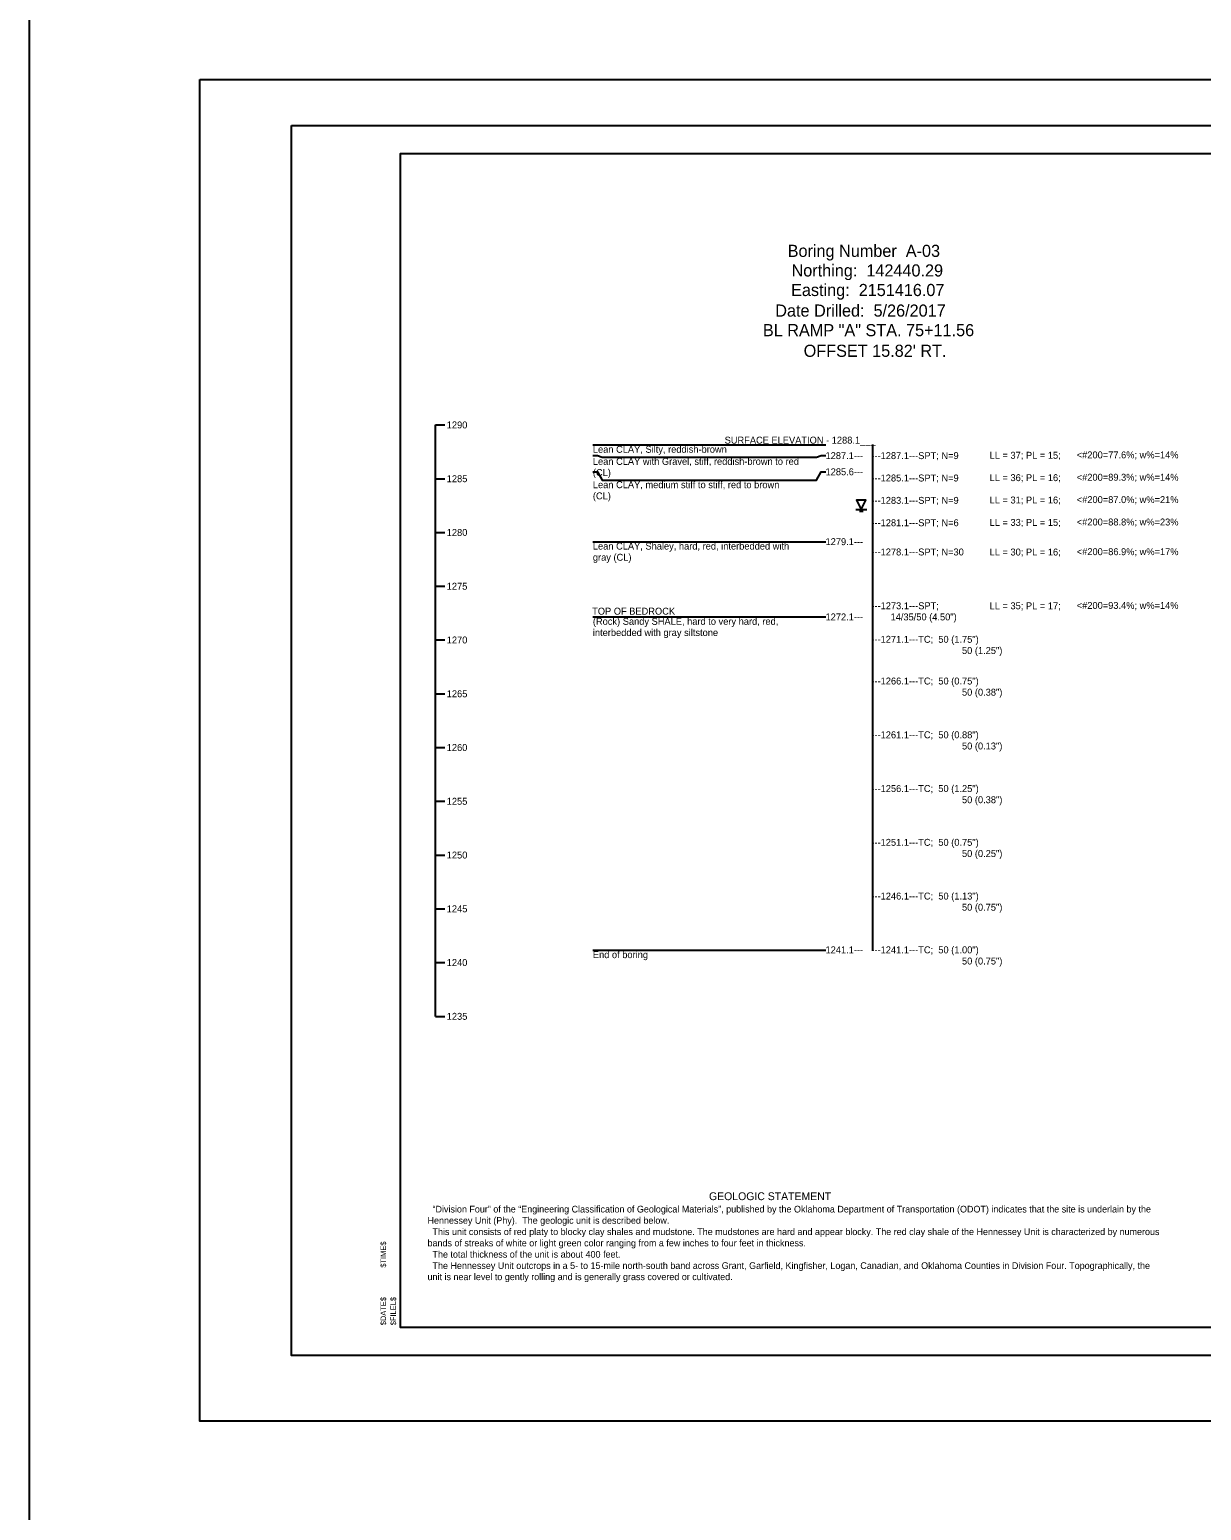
# Model space of a CAD drawing. Extents: x 2150161.5 to 2150203.1, y 143779.5 to 143868.5.
# Drawn here: x 2150161.53 to 2150182.49, y 143808.09 to 143834.58 of the extents above; entities that cross this region are included whole.
import ezdxf

# ---------------------------------------------------------------- set-up
doc = ezdxf.new("R2010")
doc.units = 0
for name, color, linetype in [('Default', 7, 'Continuous'), ('S', 7, 'Continuous'), ('SHT_Plot_Shape_Full', 7, 'Continuous'), ('SHT_Plot_Shape_Half', 7, 'Continuous'), ('SHT_Plot_Stamp', 7, 'Continuous'), ('SHT_Sheet_Border', 7, 'Continuous'), ('Text', 7, 'Continuous')]:
    doc.layers.add(name, color=color, linetype=linetype)

# ---------------------------------------------------------------- blocks, each defined once
blk = doc.blocks.new('Stamp_Plot_Stamp')
at = {"layer": 'SHT_Plot_Stamp'}
for s, p in [('$TIME$', (1.695, 1.572)), ('$DATE$', (1.695, 0.542)), ('$FILEL$', (1.873, 0.542))]:
    blk.add_text(s, height=0.1, rotation=90, dxfattribs=at).set_placement(p)
blk = doc.blocks.new('DGRFC_WTLEV1')
at = {"layer": 'Default'}
for points in [[(-0.0127, 0), (0.0127, 0)], [(0, 0), (0.0106, 0.0212), (-0.0106, 0.0212), (0, 0)], [(-0.0042, -0.0042), (0.0042, -0.0042)]]:
    blk.add_lwpolyline(points, dxfattribs=at)

msp = doc.modelspace()

# ---------------------------------------------------------------- linework, layer by layer
at = {"layer": 'Default'}
msp.add_line((2150168.788, 143816.93), (2150168.788, 143827.507), dxfattribs=at)
for points in [[(2150168.788, 143827.507), (2150168.955, 143827.507)], [(2150171.606, 143827.15), (2150175.773, 143827.15)], [(2150176.606, 143827.16), (2150176.606, 143818.111)], [(2150171.606, 143826.958), (2150171.69, 143826.958), (2150171.773, 143826.933), (2150175.606, 143826.933), (2150175.69, 143826.958), (2150175.773, 143826.958)], [(2150168.788, 143826.545), (2150168.955, 143826.545)], [(2150171.606, 143826.669), (2150171.69, 143826.669), (2150171.773, 143826.517), (2150175.606, 143826.517), (2150175.69, 143826.669), (2150175.773, 143826.669)], [(2150176.606, 143826.708), (2150176.606, 143819.202)], [(2150168.788, 143825.584), (2150168.955, 143825.584)], [(2150171.606, 143825.419), (2150175.773, 143825.419)], [(2150168.788, 143824.622), (2150168.955, 143824.622)], [(2150171.606, 143824.073), (2150175.773, 143824.073)], [(2150168.788, 143823.661), (2150168.955, 143823.661)], [(2150168.788, 143822.699), (2150168.955, 143822.699)], [(2150168.788, 143821.738), (2150168.955, 143821.738)], [(2150168.788, 143820.776), (2150168.955, 143820.776)], [(2150168.788, 143819.815), (2150168.955, 143819.815)], [(2150168.788, 143818.853), (2150168.955, 143818.853)], [(2150168.788, 143818.853), (2150168.955, 143818.853)], [(2150171.606, 143818.111), (2150175.773, 143818.111)], [(2150168.788, 143817.892), (2150168.955, 143817.892)], [(2150168.788, 143817.892), (2150168.955, 143817.892)], [(2150168.788, 143816.93), (2150168.955, 143816.93)], [(2150168.788, 143816.93), (2150168.955, 143816.93)], [(2150168.788, 143816.93), (2150168.955, 143816.93)]]:
    msp.add_lwpolyline(points, dxfattribs=at)
at = {"layer": 'S'}
msp.add_lwpolyline([(2150161.53, 143868.477), (2150203.071, 143868.477), (2150203.071, 143779.536), (2150161.53, 143779.536)], close=True, dxfattribs=at)
at = {"layer": 'SHT_Plot_Shape_Full'}
msp.add_lwpolyline([(2150164.575, 143833.688), (2150200.575, 143833.688), (2150200.575, 143809.688), (2150164.575, 143809.688)], close=True, dxfattribs=at)
at = {"layer": 'SHT_Plot_Shape_Half'}
msp.add_lwpolyline([(2150166.212, 143832.863), (2150200.212, 143832.863), (2150200.212, 143810.863), (2150166.212, 143810.863)], close=True, dxfattribs=at)
at = {"layer": 'SHT_Sheet_Border'}
msp.add_lwpolyline([(2150199.662, 143811.363), (2150168.162, 143811.363), (2150168.162, 143832.363), (2150199.662, 143832.363)], close=True, dxfattribs=at)

# ---------------------------------------------------------------- block references
at = {"layer": 'Default', "xscale": 7.873999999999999, "yscale": 7.873999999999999}
msp.add_blockref('DGRFC_WTLEV1', (2150176.408, 143825.996), dxfattribs=at)
at = {"layer": 'SHT_Plot_Stamp'}
msp.add_blockref('Stamp_Plot_Stamp', (2150166.212, 143810.863), dxfattribs=at)

# ---------------------------------------------------------------- texts
at = {"layer": 'Default'}
for s, height, p in [('Boring Number  A-03', 0.217, (2150175.091, 143830.512)), ('Northing:  142440.29', 0.217, (2150175.16, 143830.162)), ('Easting:  2151416.07', 0.217, (2150175.152, 143829.812)), ('Date Drilled:  5/26/2017', 0.217, (2150174.869, 143829.444)), ('BL RAMP "A" STA. 75+11.56', 0.217, (2150174.648, 143829.094)), ("OFFSET 15.82' RT.", 0.217, (2150175.377, 143828.725)), ('1290', 0.124, (2150168.992, 143827.445)), ('Lean CLAY, Silty, reddish-brown', 0.124, (2150171.606, 143827.009)), ('SURFACE ELEVATION - 1288.1___', 0.124, (2150173.963, 143827.173)), ('Lean CLAY with Gravel, stiff, reddish-brown to red', 0.124, (2150171.606, 143826.793)), ('1287.1---', 0.124, (2150175.768, 143826.896)), ('---1287.1---SPT; N=9', 0.124, (2150176.588, 143826.896)), ('LL = 37; PL = 15;', 0.124, (2150178.703, 143826.902)), ('<#200=77.6%; w%=14%', 0.124, (2150180.262, 143826.909)), ('1285', 0.124, (2150168.992, 143826.483)), ('(CL)', 0.124, (2150171.606, 143826.593)), ('1285.6---', 0.124, (2150175.768, 143826.607)), ('---1285.1---SPT; N=9', 0.124, (2150176.588, 143826.496)), ('LL = 36; PL = 16;', 0.124, (2150178.703, 143826.502)), ('<#200=89.3%; w%=14%', 0.124, (2150180.262, 143826.509)), ('(CL)', 0.124, (2150171.606, 143826.176)), ('Lean CLAY, medium stiff to stiff, red to brown', 0.124, (2150171.606, 143826.376)), ('---1283.1---SPT; N=9', 0.124, (2150176.588, 143826.096)), ('LL = 31; PL = 16;', 0.124, (2150178.703, 143826.102)), ('<#200=87.0%; w%=21%', 0.124, (2150180.262, 143826.109)), ('---1281.1---SPT; N=6', 0.124, (2150176.588, 143825.696)), ('LL = 33; PL = 15;', 0.124, (2150178.703, 143825.702)), ('<#200=88.8%; w%=23%', 0.124, (2150180.262, 143825.709)), ('1280', 0.124, (2150168.992, 143825.522)), ('1279.1---', 0.124, (2150175.768, 143825.357)), ('gray (CL)', 0.124, (2150171.606, 143825.078)), ('Lean CLAY, Shaley, hard, red, interbedded with', 0.124, (2150171.606, 143825.278)), ('---1278.1---SPT; N=30', 0.124, (2150176.588, 143825.173)), ('LL = 30; PL = 16;', 0.124, (2150178.703, 143825.172)), ('<#200=86.9%; w%=17%', 0.124, (2150180.262, 143825.178)), ('1275', 0.124, (2150168.992, 143824.56)), ('TOP OF BEDROCK', 0.124, (2150171.593, 143824.114)), ('1272.1---', 0.124, (2150175.768, 143824.011)), ('---1273.1---SPT;', 0.124, (2150176.588, 143824.211)), ('14/35/50 (4.50")', 0.124, (2150176.931, 143824.011)), ('LL = 35; PL = 17;', 0.124, (2150178.703, 143824.21)), ('<#200=93.4%; w%=14%', 0.124, (2150180.262, 143824.217)), ('(Rock) Sandy SHALE, hard to very hard, red,', 0.124, (2150171.606, 143823.932)), ('interbedded with gray siltstone', 0.124, (2150171.606, 143823.732)), ('1270', 0.124, (2150168.992, 143823.599)), ('---1271.1---TC;  50 (1.75")', 0.124, (2150176.588, 143823.611)), ('50 (1.25")', 0.124, (2150178.209, 143823.411)), ('---1266.1---TC;  50 (0.75")', 0.124, (2150176.588, 143822.865)), ('1265', 0.124, (2150168.992, 143822.637)), ('50 (0.38")', 0.124, (2150178.209, 143822.665)), ('---1261.1---TC;  50 (0.88")', 0.124, (2150176.588, 143821.903)), ('1260', 0.124, (2150168.992, 143821.676)), ('50 (0.13")', 0.124, (2150178.209, 143821.703)), ('---1256.1---TC;  50 (1.25")', 0.124, (2150176.588, 143820.942)), ('1255', 0.124, (2150168.992, 143820.714)), ('50 (0.38")', 0.124, (2150178.209, 143820.742)), ('---1251.1---TC;  50 (0.75")', 0.124, (2150176.588, 143819.98)), ('50 (0.25")', 0.124, (2150178.209, 143819.78)), ('1250', 0.124, (2150168.992, 143819.753)), ('---1246.1---TC;  50 (1.13")', 0.124, (2150176.588, 143819.019)), ('1245', 0.124, (2150168.992, 143818.791)), ('50 (0.75")', 0.124, (2150178.209, 143818.819)), ('End of boring', 0.124, (2150171.606, 143817.971)), ('1241.1---', 0.124, (2150175.768, 143818.057)), ('---1241.1---TC;  50 (1.00")', 0.124, (2150176.588, 143818.057)), ('1240', 0.124, (2150168.992, 143817.83)), ('50 (0.75")', 0.124, (2150178.209, 143817.857)), ('1235', 0.124, (2150168.992, 143816.868))]:
    msp.add_text(s, height=height, dxfattribs=at).set_placement(p)
at = {"layer": 'Text'}
for s, height, p in [('  “Division Four” of the “Engineering Classification of Geological Materials”, published by the Oklahoma Department of Transportation (ODOT) indicates that the site is underlain by the ', 0.12, (2150168.648, 143813.422)), ('GEOLOGIC STATEMENT', 0.14, (2150173.684, 143813.643)), ('Hennessey Unit (Phy).  The geologic unit is described below. ', 0.12, (2150168.648, 143813.22)), ('  This unit consists of red platy to blocky clay shales and mudstone. The mudstones are hard and appear blocky. The red clay shale of the Hennessey Unit is characterized by numerous ', 0.12, (2150168.648, 143813.018)), ('bands of streaks of white or light green color ranging from a few inches to four feet in thickness. ', 0.12, (2150168.648, 143812.816)), ('  The total thickness of the unit is about 400 feet.', 0.12, (2150168.648, 143812.614)), ('  The Hennessey Unit outcrops in a 5- to 15-mile north-south band across Grant, Garfield, Kingfisher, Logan, Canadian, and Oklahoma Counties in Division Four. Topographically, the ', 0.12, (2150168.648, 143812.412)), ('unit is near level to gently rolling and is generally grass covered or cultivated.', 0.12, (2150168.648, 143812.212))]:
    msp.add_text(s, height=height, dxfattribs=at).set_placement(p)

doc.saveas('drawing.dxf')
